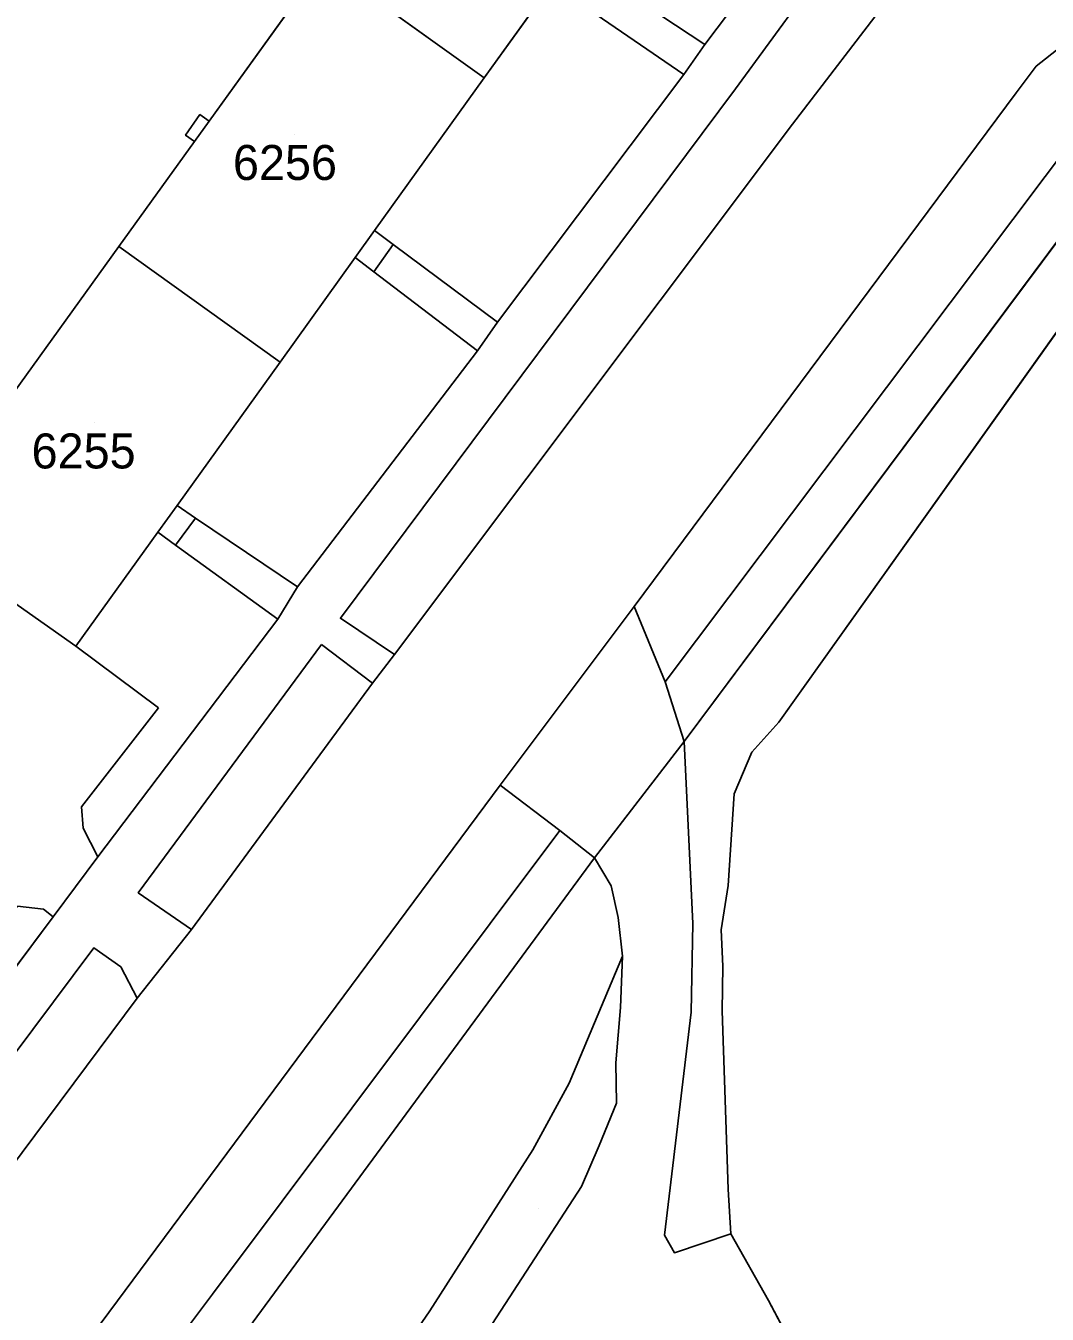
# Model space of a CAD drawing. Extents: x -266199 to -261993, y -1239047 to -1235108.
# Drawn here: x -263788.8 to -263730.4, y -1236538.8 to -1236465.2 of the extents above; entities that cross this region are included whole.
import ezdxf

# ---------------------------------------------------------------- set-up
doc = ezdxf.new("R2010")
doc.units = 0
for name, color, linetype in [('body_kn', 7, 'Continuous'), ('kladpar_druhypozemkov', 7, 'Continuous'), ('kladpar_hranice', 7, 'Continuous'), ('kladpar_parcelnecisla', 7, 'Continuous'), ('kladpar_plochy', 7, 'Continuous'), ('zappar_hrandruhpozemk', 7, 'Continuous')]:
    doc.layers.add(name, color=color, linetype=linetype)

msp = doc.modelspace()

# ---------------------------------------------------------------- linework, layer by layer
at = {"layer": 'body_kn'}
for p, q in [((-263749.99, -1236466.25), (-263749.99, -1236466.25)), ((-263749.99, -1236466.25), (-263749.99, -1236466.25)), ((-263751.19, -1236467.97), (-263751.19, -1236467.97)), ((-263731.04, -1236467.5), (-263731.04, -1236467.5)), ((-263762.61, -1236468.17), (-263762.61, -1236468.17)), ((-263762.61, -1236468.17), (-263762.61, -1236468.17)), ((-263748.24, -1236468.79), (-263748.24, -1236468.79)), ((-263732.2, -1236469.01), (-263732.2, -1236469.01)), ((-263778.87, -1236470.26), (-263778.87, -1236470.26)), ((-263778.34, -1236470.63), (-263778.34, -1236470.63)), ((-263744.99, -1236470.81), (-263744.99, -1236470.81)), ((-263779.69, -1236471.44), (-263779.69, -1236471.44)), ((-263779.19, -1236471.8), (-263779.19, -1236471.8)), ((-263779.19, -1236471.8), (-263779.19, -1236471.8)), ((-263768.88, -1236476.89), (-263768.88, -1236476.89)), ((-263768.88, -1236476.89), (-263768.88, -1236476.89)), ((-263767.82, -1236477.68), (-263767.82, -1236477.68)), ((-263783.5, -1236477.8), (-263783.5, -1236477.8)), ((-263783.5, -1236477.8), (-263783.5, -1236477.8)), ((-263770, -1236478.44), (-263770, -1236478.44)), ((-263768.93, -1236479.25), (-263768.93, -1236479.25)), ((-263768.93, -1236479.25), (-263768.93, -1236479.25)), ((-263761.86, -1236482.12), (-263761.86, -1236482.12)), ((-263761.86, -1236482.12), (-263761.86, -1236482.12)), ((-263762.99, -1236483.76), (-263762.99, -1236483.76)), ((-263774.29, -1236484.41), (-263774.29, -1236484.41)), ((-263774.29, -1236484.41), (-263774.29, -1236484.41)), ((-263780.18, -1236492.61), (-263780.18, -1236492.61)), ((-263780.18, -1236492.61), (-263780.18, -1236492.61)), ((-263779.12, -1236493.33), (-263779.12, -1236493.33)), ((-263781.28, -1236494.14), (-263781.28, -1236494.14)), ((-263780.26, -1236494.88), (-263780.26, -1236494.88)), ((-263780.26, -1236494.88), (-263780.26, -1236494.88)), ((-263773.29, -1236497.25), (-263773.29, -1236497.25)), ((-263773.29, -1236497.25), (-263773.29, -1236497.25)), ((-263754.04, -1236498.39), (-263754.04, -1236498.39)), ((-263754.04, -1236498.39), (-263754.04, -1236498.39)), ((-263774.42, -1236499.1), (-263774.42, -1236499.1)), ((-263770.84, -1236499.05), (-263770.84, -1236499.05)), ((-263785.96, -1236500.65), (-263785.96, -1236500.65)), ((-263771.92, -1236500.55), (-263771.92, -1236500.55)), ((-263771.92, -1236500.55), (-263771.92, -1236500.55)), ((-263767.75, -1236501.13), (-263767.75, -1236501.13)), ((-263752.27, -1236502.68), (-263752.27, -1236502.68)), ((-263769, -1236502.77), (-263769, -1236502.77)), ((-263769, -1236502.77), (-263769, -1236502.77)), ((-263781.24, -1236504.18), (-263781.24, -1236504.18)), ((-263745.77, -1236505), (-263745.77, -1236505)), ((-263751.17, -1236506.09), (-263751.17, -1236506.09)), ((-263751.17, -1236506.09), (-263751.17, -1236506.09)), ((-263747.3, -1236506.7), (-263747.3, -1236506.7)), ((-263761.7, -1236508.59), (-263761.7, -1236508.59)), ((-263761.7, -1236508.59), (-263761.7, -1236508.59)), ((-263748.32, -1236509.1), (-263748.32, -1236509.1)), ((-263785.65, -1236509.84), (-263785.65, -1236509.84)), ((-263785.54, -1236511.05), (-263785.54, -1236511.05)), ((-263758.29, -1236511.18), (-263758.29, -1236511.18)), ((-263784.71, -1236512.7), (-263784.71, -1236512.7)), ((-263784.71, -1236512.7), (-263784.71, -1236512.7)), ((-263756.31, -1236512.75), (-263756.31, -1236512.75)), ((-263756.31, -1236512.75), (-263756.31, -1236512.75)), ((-263755.35, -1236514.35), (-263755.35, -1236514.35)), ((-263748.67, -1236514.33), (-263748.67, -1236514.33)), ((-263782.4, -1236514.75), (-263782.4, -1236514.75)), ((-263787.82, -1236515.68), (-263787.82, -1236515.68)), ((-263787.26, -1236516.13), (-263787.26, -1236516.13)), ((-263754.95, -1236516.16), (-263754.95, -1236516.16)), ((-263750.69, -1236516.5), (-263750.69, -1236516.5)), ((-263779.35, -1236516.85), (-263779.35, -1236516.85)), ((-263779.35, -1236516.85), (-263779.35, -1236516.85)), ((-263749.06, -1236516.87), (-263749.06, -1236516.87)), ((-263784.93, -1236517.89), (-263784.93, -1236517.89)), ((-263754.7, -1236518.38), (-263754.7, -1236518.38)), ((-263783.4, -1236518.98), (-263783.4, -1236518.98)), ((-263748.96, -1236518.94), (-263748.96, -1236518.94)), ((-263782.46, -1236520.77), (-263782.46, -1236520.77)), ((-263782.46, -1236520.77), (-263782.46, -1236520.77)), ((-263754.82, -1236521.31), (-263754.82, -1236521.31)), ((-263750.78, -1236521.58), (-263750.78, -1236521.58)), ((-263749.01, -1236521.49), (-263749.01, -1236521.49)), ((-263755.09, -1236524.47), (-263755.09, -1236524.47)), ((-263757.76, -1236525.63), (-263757.76, -1236525.63)), ((-263757.76, -1236525.63), (-263757.76, -1236525.63)), ((-263755.05, -1236526.77), (-263755.05, -1236526.77)), ((-263756.04, -1236529.2), (-263756.04, -1236529.2)), ((-263759.84, -1236529.44), (-263759.84, -1236529.44)), ((-263757.05, -1236531.53), (-263757.05, -1236531.53)), ((-263748.66, -1236531.7), (-263748.66, -1236531.7)), ((-263752.3, -1236534.32), (-263752.3, -1236534.32)), ((-263748.51, -1236534.24), (-263748.51, -1236534.24)), ((-263751.74, -1236535.33), (-263751.74, -1236535.33)), ((-263778.16, -1236537.69), (-263778.16, -1236537.69)), ((-263746.36, -1236538.05), (-263746.36, -1236538.05)), ((-263765.72, -1236538.65), (-263765.72, -1236538.65))]:
    msp.add_line(p, q, dxfattribs=at)
at = {"layer": 'kladpar_druhypozemkov'}
for p, q in [((-263773.44, -1236471.4), (-263773.44, -1236471.4)), ((-263784.9, -1236487.89), (-263784.9, -1236487.89)), ((-263759.5, -1236532.78), (-263759.5, -1236532.78))]:
    msp.add_line(p, q, dxfattribs=at)
at = {"layer": 'kladpar_hranice'}
for p, q in [((-263762.61, -1236468.17), (-263771.82, -1236461.57)), ((-263771.82, -1236461.57), (-263762.61, -1236468.17)), ((-263774.29, -1236484.41), (-263783.5, -1236477.8)), ((-263783.5, -1236477.8), (-263774.29, -1236484.41))]:
    msp.add_line(p, q, dxfattribs=at)
for points in [[(-263771.82, -1236461.57), (-263767.86, -1236456.07), (-263768.36, -1236455.79), (-263767.53, -1236454.58), (-263767.05, -1236454.96), (-263762.27, -1236448.31), (-263753.11, -1236454.95), (-263757.62, -1236461.22), (-263756.47, -1236461.98), (-263757.6, -1236463.56), (-263758.74, -1236462.78), (-263762.61, -1236468.17)], [(-263891.8, -1236662.79), (-263884.21, -1236662.21), (-263883.76, -1236662.18), (-263855.91, -1236618.77), (-263857.79, -1236605.66), (-263849.82, -1236608.89), (-263847.85, -1236609.69), (-263838.71, -1236596.56), (-263820.36, -1236571.56), (-263803.78, -1236549.4), (-263802.64, -1236547.8), (-263805.88, -1236545.91), (-263808.37, -1236543.71), (-263797.61, -1236529.86), (-263796.45, -1236528.4), (-263787.26, -1236516.13), (-263784.71, -1236512.7), (-263774.42, -1236499.1), (-263773.29, -1236497.25), (-263762.99, -1236483.76), (-263761.86, -1236482.12), (-263751.19, -1236467.97), (-263749.99, -1236466.25), (-263745.24, -1236459.93)], [(-263745.24, -1236459.93), (-263749.99, -1236466.25), (-263751.19, -1236467.97), (-263761.86, -1236482.12), (-263762.99, -1236483.76), (-263773.29, -1236497.25), (-263774.42, -1236499.1), (-263784.71, -1236512.7), (-263787.26, -1236516.13), (-263796.45, -1236528.4), (-263797.61, -1236529.86), (-263808.37, -1236543.71), (-263805.88, -1236545.91), (-263802.64, -1236547.8), (-263803.78, -1236549.4), (-263820.36, -1236571.56)], [(-263771.82, -1236461.57), (-263778.34, -1236470.63), (-263778.87, -1236470.26), (-263779.69, -1236471.44), (-263779.19, -1236471.8), (-263783.5, -1236477.8), (-263789.57, -1236486.23), (-263790.04, -1236485.86), (-263790.89, -1236487.01), (-263790.39, -1236487.37), (-263795.19, -1236494.03), (-263797.04, -1236496.76), (-263798.73, -1236499.26), (-263800.41, -1236501.74), (-263802.1, -1236504.23), (-263803.8, -1236506.73), (-263805.49, -1236509.22), (-263807.22, -1236511.78), (-263810.44, -1236509.57), (-263820.84, -1236524.81), (-263831.66, -1236540.67)], [(-263783.5, -1236477.8), (-263779.19, -1236471.8), (-263779.69, -1236471.44), (-263778.87, -1236470.26), (-263778.34, -1236470.63), (-263771.82, -1236461.57)], [(-263789.58, -1236498.09), (-263785.96, -1236500.65), (-263781.28, -1236494.14), (-263780.26, -1236494.88), (-263779.12, -1236493.33), (-263780.18, -1236492.61), (-263774.29, -1236484.41), (-263770, -1236478.44), (-263768.93, -1236479.25), (-263767.82, -1236477.68), (-263768.88, -1236476.89), (-263762.61, -1236468.17), (-263758.74, -1236462.78)], [(-263762.61, -1236468.17), (-263768.88, -1236476.89), (-263767.82, -1236477.68), (-263768.93, -1236479.25), (-263770, -1236478.44), (-263774.29, -1236484.41)], [(-263720.79, -1236469.94), (-263745.77, -1236505), (-263747.3, -1236506.7), (-263748.32, -1236509.1), (-263748.67, -1236514.33), (-263749.06, -1236516.87), (-263748.96, -1236518.94), (-263749.01, -1236521.49), (-263748.66, -1236531.7), (-263748.51, -1236534.24), (-263746.36, -1236538.05), (-263743.31, -1236543.79), (-263751.82, -1236557.5), (-263820.05, -1236667.43)], [(-263743.31, -1236543.79), (-263746.36, -1236538.05), (-263748.51, -1236534.24), (-263748.66, -1236531.7), (-263749.01, -1236521.49), (-263748.96, -1236518.94), (-263749.06, -1236516.87), (-263748.67, -1236514.33), (-263748.32, -1236509.1), (-263747.3, -1236506.7), (-263745.77, -1236505), (-263720.79, -1236469.94)], [(-263846.37, -1236629.67), (-263844.57, -1236626.81), (-263836.23, -1236614.05), (-263834.06, -1236611.01), (-263832.46, -1236608.68), (-263830.63, -1236607.02), (-263828.45, -1236606.01), (-263824.16, -1236603.87), (-263798.03, -1236568.9), (-263797.02, -1236567.47), (-263776.09, -1236539.64), (-263756.31, -1236512.75), (-263751.17, -1236506.09), (-263724.51, -1236470.36)], [(-263724.51, -1236470.36), (-263751.17, -1236506.09), (-263756.31, -1236512.75), (-263776.09, -1236539.64), (-263797.02, -1236567.47), (-263798.03, -1236568.9), (-263824.16, -1236603.87), (-263828.45, -1236606.01), (-263830.63, -1236607.02), (-263832.46, -1236608.68), (-263834.06, -1236611.01), (-263836.23, -1236614.05), (-263844.57, -1236626.81), (-263846.37, -1236629.67)], [(-263795.19, -1236494.03), (-263790.39, -1236487.37), (-263790.89, -1236487.01), (-263790.04, -1236485.86), (-263789.57, -1236486.23), (-263783.5, -1236477.8)], [(-263774.29, -1236484.41), (-263780.18, -1236492.61), (-263779.12, -1236493.33), (-263780.26, -1236494.88), (-263781.28, -1236494.14), (-263785.96, -1236500.65), (-263789.58, -1236498.09), (-263795.19, -1236494.03)]]:
    msp.add_lwpolyline(points, dxfattribs=at)
at = {"layer": 'kladpar_plochy'}
for p, q in [((-263745.24, -1236459.93), (-263749.99, -1236466.25)), ((-263771.82, -1236461.57), (-263778.34, -1236470.63)), ((-263762.61, -1236468.17), (-263758.74, -1236462.78)), ((-263749.99, -1236466.25), (-263751.19, -1236467.97)), ((-263751.19, -1236467.97), (-263761.86, -1236482.12)), ((-263768.88, -1236476.89), (-263762.61, -1236468.17)), ((-263778.87, -1236470.26), (-263779.69, -1236471.44)), ((-263778.34, -1236470.63), (-263778.87, -1236470.26)), ((-263720.79, -1236469.94), (-263745.77, -1236505)), ((-263751.17, -1236506.09), (-263724.51, -1236470.36)), ((-263779.69, -1236471.44), (-263779.19, -1236471.8)), ((-263779.19, -1236471.8), (-263783.5, -1236477.8)), ((-263767.82, -1236477.68), (-263768.88, -1236476.89)), ((-263768.93, -1236479.25), (-263767.82, -1236477.68)), ((-263783.5, -1236477.8), (-263789.57, -1236486.23)), ((-263774.29, -1236484.41), (-263770, -1236478.44)), ((-263770, -1236478.44), (-263768.93, -1236479.25)), ((-263761.86, -1236482.12), (-263762.99, -1236483.76)), ((-263762.99, -1236483.76), (-263773.29, -1236497.25)), ((-263780.18, -1236492.61), (-263774.29, -1236484.41)), ((-263779.12, -1236493.33), (-263780.18, -1236492.61)), ((-263780.26, -1236494.88), (-263779.12, -1236493.33)), ((-263785.96, -1236500.65), (-263781.28, -1236494.14)), ((-263781.28, -1236494.14), (-263780.26, -1236494.88)), ((-263773.29, -1236497.25), (-263774.42, -1236499.1)), ((-263789.58, -1236498.09), (-263785.96, -1236500.65)), ((-263774.42, -1236499.1), (-263784.71, -1236512.7)), ((-263745.77, -1236505), (-263747.3, -1236506.7)), ((-263756.31, -1236512.75), (-263751.17, -1236506.09)), ((-263747.3, -1236506.7), (-263748.32, -1236509.1)), ((-263748.32, -1236509.1), (-263748.67, -1236514.33)), ((-263784.71, -1236512.7), (-263787.26, -1236516.13)), ((-263776.09, -1236539.64), (-263756.31, -1236512.75)), ((-263748.67, -1236514.33), (-263749.06, -1236516.87)), ((-263787.26, -1236516.13), (-263796.45, -1236528.4)), ((-263749.06, -1236516.87), (-263748.96, -1236518.94)), ((-263748.96, -1236518.94), (-263749.01, -1236521.49)), ((-263749.01, -1236521.49), (-263748.66, -1236531.7)), ((-263748.66, -1236531.7), (-263748.51, -1236534.24)), ((-263748.51, -1236534.24), (-263746.36, -1236538.05)), ((-263746.36, -1236538.05), (-263743.31, -1236543.79))]:
    msp.add_line(p, q, dxfattribs=at)
for points in [[(-263771.82, -1236461.57), (-263767.86, -1236456.07), (-263768.36, -1236455.79), (-263767.53, -1236454.58), (-263767.05, -1236454.96), (-263762.27, -1236448.31), (-263753.11, -1236454.95), (-263757.62, -1236461.22), (-263756.47, -1236461.98), (-263757.6, -1236463.56), (-263758.74, -1236462.78), (-263762.61, -1236468.17)], [(-263783.5, -1236477.8), (-263779.19, -1236471.8), (-263779.69, -1236471.44), (-263778.87, -1236470.26), (-263778.34, -1236470.63), (-263771.82, -1236461.57), (-263762.61, -1236468.17), (-263768.88, -1236476.89), (-263767.82, -1236477.68), (-263768.93, -1236479.25), (-263770, -1236478.44), (-263774.29, -1236484.41)], [(-263795.19, -1236494.03), (-263790.39, -1236487.37), (-263790.89, -1236487.01), (-263790.04, -1236485.86), (-263789.57, -1236486.23), (-263783.5, -1236477.8), (-263774.29, -1236484.41), (-263780.18, -1236492.61), (-263779.12, -1236493.33), (-263780.26, -1236494.88), (-263781.28, -1236494.14), (-263785.96, -1236500.65), (-263789.58, -1236498.09)]]:
    msp.add_lwpolyline(points, close=True, dxfattribs=at)
for points in [[(-263883.76, -1236662.18), (-263855.91, -1236618.77), (-263857.79, -1236605.66), (-263849.82, -1236608.89), (-263847.85, -1236609.69), (-263838.71, -1236596.56), (-263820.36, -1236571.56), (-263803.78, -1236549.4), (-263802.64, -1236547.8), (-263805.88, -1236545.91), (-263808.37, -1236543.71), (-263797.61, -1236529.86), (-263796.45, -1236528.4), (-263787.26, -1236516.13), (-263784.71, -1236512.7), (-263774.42, -1236499.1), (-263773.29, -1236497.25), (-263762.99, -1236483.76), (-263761.86, -1236482.12), (-263751.19, -1236467.97), (-263749.99, -1236466.25), (-263745.24, -1236459.93)], [(-263674.85, -1236633.55), (-263818.23, -1236668.04), (-263820.05, -1236667.43), (-263751.82, -1236557.5), (-263743.31, -1236543.79), (-263746.36, -1236538.05), (-263748.51, -1236534.24), (-263748.66, -1236531.7), (-263749.01, -1236521.49), (-263748.96, -1236518.94), (-263749.06, -1236516.87), (-263748.67, -1236514.33), (-263748.32, -1236509.1), (-263747.3, -1236506.7), (-263745.77, -1236505), (-263720.79, -1236469.94)], [(-263724.51, -1236470.36), (-263751.17, -1236506.09), (-263756.31, -1236512.75), (-263776.09, -1236539.64), (-263797.02, -1236567.47), (-263798.03, -1236568.9), (-263824.16, -1236603.87), (-263828.45, -1236606.01), (-263830.63, -1236607.02), (-263832.46, -1236608.68), (-263834.06, -1236611.01), (-263836.23, -1236614.05), (-263844.57, -1236626.81), (-263846.37, -1236629.67)]]:
    msp.add_lwpolyline(points, dxfattribs=at)
at = {"layer": 'zappar_hrandruhpozemk'}
for p, q in [((-263749.99, -1236466.25), (-263756.47, -1236461.98)), ((-263742.92, -1236461.51), (-263748.24, -1236468.79)), ((-263757.6, -1236463.56), (-263751.19, -1236467.97)), ((-263726.77, -1236468.78), (-263752.27, -1236502.68)), ((-263732.2, -1236469.01), (-263754.04, -1236498.39)), ((-263779.19, -1236471.8), (-263778.34, -1236470.63)), ((-263744.99, -1236470.81), (-263767.75, -1236501.13)), ((-263768.88, -1236476.89), (-263770, -1236478.44)), ((-263761.86, -1236482.12), (-263767.82, -1236477.68)), ((-263768.93, -1236479.25), (-263762.99, -1236483.76)), ((-263780.18, -1236492.61), (-263781.28, -1236494.14)), ((-263773.29, -1236497.25), (-263779.12, -1236493.33)), ((-263780.26, -1236494.88), (-263774.42, -1236499.1)), ((-263754.04, -1236498.39), (-263761.7, -1236508.59)), ((-263781.24, -1236504.18), (-263785.96, -1236500.65)), ((-263771.92, -1236500.55), (-263769, -1236502.77)), ((-263769, -1236502.77), (-263779.35, -1236516.85)), ((-263829.05, -1236599.3), (-263761.7, -1236508.59)), ((-263756.31, -1236512.75), (-263758.29, -1236511.18)), ((-263782.46, -1236520.77), (-263779.35, -1236516.85)), ((-263802.64, -1236547.8), (-263782.46, -1236520.77)), ((-263750.78, -1236521.58), (-263752.3, -1236534.32)), ((-263759.84, -1236529.44), (-263757.76, -1236525.63)), ((-263765.72, -1236538.65), (-263759.84, -1236529.44)), ((-263757.05, -1236531.53), (-263764.59, -1236543.14)), ((-263778.16, -1236537.69), (-263825.11, -1236600.32))]:
    msp.add_line(p, q, dxfattribs=at)
for points in [[(-263742.92, -1236461.51), (-263736.98, -1236453.62), (-263733.83, -1236455.88), (-263739.39, -1236463.52), (-263744.99, -1236470.81)], [(-263728.1, -1236465.67), (-263729.61, -1236466.37), (-263731.04, -1236467.5), (-263732.2, -1236469.01)], [(-263748.24, -1236468.79), (-263770.84, -1236499.05), (-263767.75, -1236501.13), (-263769, -1236502.77)], [(-263751.17, -1236506.09), (-263752.27, -1236502.68), (-263754.04, -1236498.39)], [(-263779.35, -1236516.85), (-263782.4, -1236514.75), (-263771.92, -1236500.55)], [(-263784.71, -1236512.7), (-263785.54, -1236511.05), (-263785.65, -1236509.84), (-263781.24, -1236504.18)], [(-263751.17, -1236506.09), (-263750.69, -1236516.5), (-263750.78, -1236521.58)], [(-263761.7, -1236508.59), (-263758.29, -1236511.18), (-263778.16, -1236537.69)], [(-263756.31, -1236512.75), (-263755.35, -1236514.35), (-263754.95, -1236516.16), (-263754.7, -1236518.38)], [(-263793.64, -1236521.08), (-263789.3, -1236515.52), (-263787.82, -1236515.68), (-263787.26, -1236516.13)], [(-263805.88, -1236545.91), (-263784.93, -1236517.89), (-263783.4, -1236518.98), (-263782.46, -1236520.77)], [(-263757.76, -1236525.63), (-263754.7, -1236518.38), (-263754.82, -1236521.31), (-263755.09, -1236524.47), (-263755.05, -1236526.77), (-263756.04, -1236529.2), (-263757.05, -1236531.53)], [(-263752.3, -1236534.32), (-263751.74, -1236535.33), (-263748.51, -1236534.24)], [(-263764.59, -1236543.14), (-263765.4, -1236543.83), (-263766.51, -1236544.01), (-263768.35, -1236542.48), (-263765.72, -1236538.65)]]:
    msp.add_lwpolyline(points, dxfattribs=at)

# ---------------------------------------------------------------- texts
at = {"layer": 'kladpar_parcelnecisla'}
for s, p in [('6256', (-263776.982, -1236474)), ('6255', (-263788.497, -1236490.49))]:
    msp.add_text(s, height=2, dxfattribs=at).set_placement(p)

doc.saveas('drawing.dxf')
